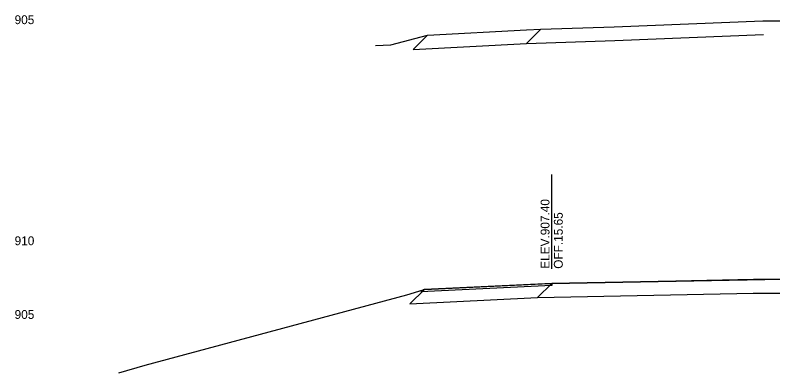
# Model space of a CAD drawing. Extents: x -4 to 359, y 0 to 1436.
# Drawn here: x 200.5 to 251.9, y 1356.3 to 1380.6 of the extents above; entities that cross this region are included whole.
import ezdxf

# ---------------------------------------------------------------- set-up
doc = ezdxf.new("R2010")
doc.units = 0
for name, color, linetype in [('XS-Existing subsurface-pavement', 7, 'Continuous'), ('XS-Existing subsurface-shoulder', 7, 'Continuous'), ('XS-Existing surface-ground', 7, 'Continuous'), ('XS-Proposed Finish Grade', 7, 'Continuous'), ('XS-Proposed surface-ground', 7, 'Continuous'), ('XS-Proposed surface-pavement', 7, 'Continuous'), ('XS-Proposed surface-shoulder', 7, 'Continuous'), ('XS-Text-elevation', 7, 'Continuous'), ('XS-Text-pavement elevation', 7, 'Continuous'), ('XS-Text-profile report', 7, 'Continuous'), ('XS-Text-tie offset', 7, 'Continuous')]:
    doc.layers.add(name, color=color, linetype=linetype)

msp = doc.modelspace()

# ---------------------------------------------------------------- linework, layer by layer
at = {"layer": 'XS-Existing subsurface-pavement'}
for p, q in [((236.113, 1379.608), (235.143, 1378.638)), ((241.137, 1378.839), (251.225, 1379.257)), ((235.143, 1378.638), (241.129, 1378.839)), ((236.854, 1362.36), (235.896, 1361.402)), ((235.896, 1361.402), (250.554, 1361.713)), ((250.531, 1361.713), (252.497, 1361.706))]:
    msp.add_line(p, q, dxfattribs=at)
at = {"layer": 'XS-Existing subsurface-shoulder'}
for p, q in [((228.437, 1379.217), (227.447, 1378.227)), ((227.447, 1378.227), (235.143, 1378.638)), ((228.234, 1361.96), (227.24, 1360.976)), ((227.24, 1360.976), (235.896, 1361.402))]:
    msp.add_line(p, q, dxfattribs=at)
at = {"layer": 'XS-Existing surface-ground'}
for p, q in [((241.098, 1379.776), (251.186, 1380.193)), ((251.186, 1380.193), (252.5, 1380.173)), ((228.437, 1379.217), (235.138, 1379.564)), ((235.138, 1379.564), (236.113, 1379.608)), ((236.113, 1379.608), (241.098, 1379.776)), ((225.94, 1378.55), (228.437, 1379.217)), ((224.897, 1378.505), (225.94, 1378.55)), ((236.854, 1362.36), (250.534, 1362.651)), ((250.534, 1362.651), (252.5, 1362.644)), ((228.234, 1361.96), (236.219, 1362.327)), ((236.219, 1362.327), (236.854, 1362.36)), ((209.269, 1356.809), (227.031, 1361.594)), ((227.031, 1361.594), (228.135, 1361.938)), ((228.135, 1361.938), (228.234, 1361.96)), ((207.5, 1356.298), (209.269, 1356.809))]:
    msp.add_line(p, q, dxfattribs=at)
at = {"layer": 'XS-Proposed Finish Grade'}
msp.add_lwpolyline([(236.854, 1362.36), (252.5, 1362.644), (276.69, 1362.217)], dxfattribs=at)
at = {"layer": 'XS-Proposed surface-ground'}
msp.add_lwpolyline([(228.234, 1361.96), (228.135, 1361.938)], dxfattribs=at)
at = {"layer": 'XS-Proposed surface-pavement'}
for points in [[(236.854, 1362.36), (252.5, 1362.644), (276.69, 1362.217)], [(276.69, 1362.217), (252.5, 1362.644), (236.854, 1362.36)], [(236.854, 1362.36), (236.854, 1362.36)]]:
    msp.add_lwpolyline(points, dxfattribs=at)
at = {"layer": 'XS-Proposed surface-shoulder'}
for p, q in [((236.854, 1362.214), (227.97, 1361.802)), ((236.854, 1362.36), (228.234, 1361.96)), ((236.854, 1362.36), (236.854, 1362.214)), ((228.234, 1361.96), (227.97, 1361.802))]:
    msp.add_line(p, q, dxfattribs=at)
at = {"layer": 'XS-Text-tie offset'}
msp.add_line((236.854, 1363.36), (236.854, 1369.758), dxfattribs=at)

# ---------------------------------------------------------------- texts
at = {"layer": 'XS-Text-elevation'}
for s, p in [('           905           ', (197.97, 1379.959)), ('           910           ', (197.97, 1364.959)), ('           905           ', (197.97, 1359.959))]:
    msp.add_text(s, height=0.6, dxfattribs=at).set_placement(p)
at = {"layer": 'XS-Text-pavement elevation'}
for s, p in [('ELEV.907.40', (236.704, 1363.36)), ('OFF.15.65', (237.604, 1363.36))]:
    msp.add_text(s, height=0.6, rotation=90, dxfattribs=at).set_placement(p)
at = {"layer": 'XS-Text-profile report'}
for s, p in [('Pvmt_Surf_Asph_T_L', (236.839, 1362.36)), ('Pvmt_Surf_Asph_T2_L', (236.838, 1362.36))]:
    msp.add_text(s, height=0.00167, dxfattribs=at).set_placement(p)

doc.saveas('drawing.dxf')
